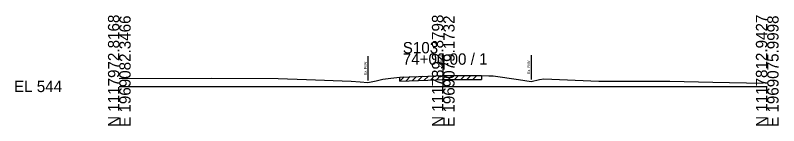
# Model space of a CAD drawing. Extents: x -26 to 163, y -10 to 24018.
# Drawn here: x -25.7 to 162.8, y 21990.3 to 22017.5 of the extents above; entities that cross this region are included whole.
import ezdxf

# ---------------------------------------------------------------- set-up
doc = ezdxf.new("R2010")
doc.units = 0
for name, color, linetype in [('RD_GPK_XS_Cell', 7, 'Continuous'), ('RD_XS_ExGround', 7, 'Continuous'), ('RD_XS_ExPaveRet', 7, 'Continuous'), ('RD_XS_ExRW', 7, 'Continuous'), ('RD_XS_TX_Elev_EX', 7, 'Continuous')]:
    doc.layers.add(name, color=color, linetype=linetype)

msp = doc.modelspace()

# ---------------------------------------------------------------- linework, layer by layer
at = {"layer": 'RD_GPK_XS_Cell'}
for p, q in [((80, 22000), (80, 22008.14)), ((0, 22000), (80, 22000)), ((80, 22000), (160, 22000))]:
    msp.add_line(p, q, dxfattribs=at)
at = {"layer": 'RD_XS_ExGround'}
msp.add_lwpolyline([(0, 22001.92), (22.77, 22001.99), (39.25, 22001.96), (46.19, 22001.7), (57.25, 22001.29), (59.49, 22001.13), (61.36, 22000.95), (63.44, 22001.38), (65.07, 22001.75), (67.04, 22002.02), (69.31, 22002.31), (76.17, 22002.54), (80, 22002.68), (81.05, 22002.71), (84.31, 22002.68), (89.45, 22002.66), (91.24, 22002.6), (92.33, 22002.57), (98.54, 22001.68), (101.68, 22001.23), (103.75, 22001.68), (104.83, 22001.87), (118.43, 22001.32), (135.95, 22001.27), (146.58, 22001.06), (159.02, 22000.83)], dxfattribs=at)
at = {"layer": 'RD_XS_ExPaveRet'}
for p, q in [((69.31, 22001.31), (70.35, 22002.35)), ((69.31, 22001.31), (69.31, 22002.31)), ((70.81, 22001.36), (71.85, 22002.4)), ((72.31, 22001.41), (73.35, 22002.45)), ((73.81, 22001.46), (74.85, 22002.5)), ((75.31, 22001.51), (76.35, 22002.55)), ((76.81, 22001.57), (77.85, 22002.6)), ((78.31, 22001.62), (79.35, 22002.65)), ((79.81, 22001.67), (80.85, 22002.71)), ((81.31, 22001.71), (82.3, 22002.7)), ((82.81, 22001.7), (83.8, 22002.69)), ((84.31, 22001.68), (85.31, 22002.68)), ((85.81, 22001.67), (86.81, 22002.67)), ((87.31, 22001.67), (88.31, 22002.66)), ((89.45, 22002.66), (89.45, 22001.66)), ((69.31, 22001.31), (76.17, 22001.54)), ((76.17, 22001.54), (80, 22001.68)), ((80, 22001.68), (81.05, 22001.71)), ((81.05, 22001.71), (84.31, 22001.68)), ((84.31, 22001.68), (89.45, 22001.66))]:
    msp.add_line(p, q, dxfattribs=at)
at = {"layer": 'RD_XS_ExRW'}
for p, q in [((61.36, 22007.45), (61.36, 22001.45)), ((101.68, 22007.73), (101.68, 22001.73))]:
    msp.add_line(p, q, dxfattribs=at)

# ---------------------------------------------------------------- texts
at = {"layer": 'RD_GPK_XS_Cell'}
for s, p in [('N 1117972.8168', (0, 21990)), ('E 1969082.3466', (2.8, 21990)), ('N 1117892.8798', (80, 21990)), ('E 1969079.1732', (82.8, 21990)), ('N 1117812.9427', (160, 21990)), ('E 1969075.9998', (162.8, 21990))]:
    msp.add_text(s, height=2.8, rotation=90, dxfattribs=at).set_placement(p)
for s, p in [('S103', (70, 22008.14)), ('74+00.00 / 1', (70, 22005.34)), ('EL 544', (-26, 21998.6))]:
    msp.add_text(s, height=2.8, dxfattribs=at).set_placement(p)
at = {"layer": 'RD_XS_ExRW'}
for p in [(61.11, 22002.79), (101.43, 22003.07)]:
    msp.add_text('Ex. R/W ', height=0.65, rotation=90, dxfattribs=at).set_placement(p)
at = {"layer": 'RD_XS_TX_Elev_EX'}
msp.add_text('546.68', height=0.8, rotation=90, dxfattribs=at).set_placement((79.9, 22004.68))

doc.saveas('drawing.dxf')
